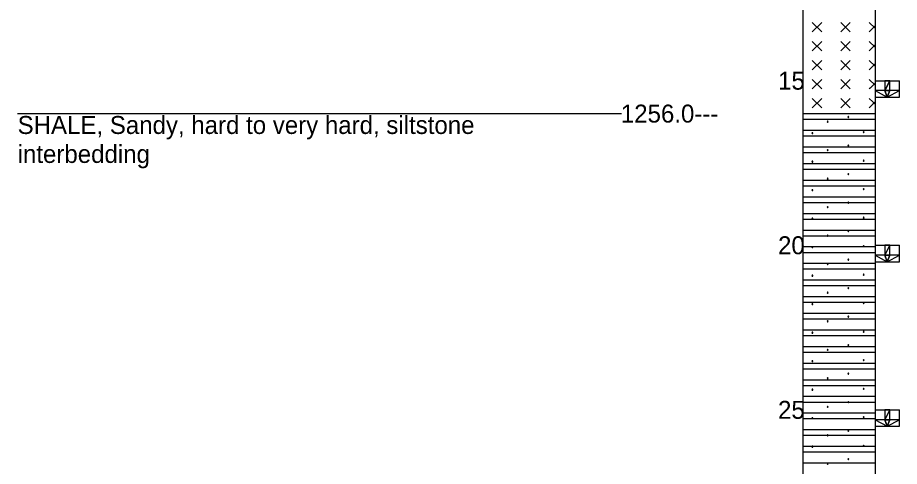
# Model space of a CAD drawing. Extents: x 2150161.5 to 2150203.1, y 143779.5 to 143868.5.
# Drawn here: x 2150186.76 to 2150192.84, y 143849.37 to 143852.47 of the extents above; entities that cross this region are included whole.
import ezdxf

# ---------------------------------------------------------------- set-up
doc = ezdxf.new("R2010")
doc.units = 0
doc.layers.add('Default', color=7, linetype='Continuous')

msp = doc.modelspace()

# ---------------------------------------------------------------- linework, layer by layer
at = {"layer": 'Default'}
for points in [[(2150192.1772, 143855.4435), (2150192.1772, 143843.2844)], [(2150192.6772, 143855.4435), (2150192.6772, 143843.2844)], [(2150192.3084, 143852.4371), (2150192.2428, 143852.3715)], [(2150192.2428, 143852.4371), (2150192.3084, 143852.3715)], [(2150192.5053, 143852.4371), (2150192.4396, 143852.3715)], [(2150192.4396, 143852.4371), (2150192.5053, 143852.3715)], [(2150192.6365, 143852.4371), (2150192.6772, 143852.3964)], [(2150192.6772, 143852.4121), (2150192.6365, 143852.3715)], [(2150192.3084, 143852.3058), (2150192.2428, 143852.2402)], [(2150192.2428, 143852.3058), (2150192.3084, 143852.2402)], [(2150192.5053, 143852.3058), (2150192.4396, 143852.2402)], [(2150192.4396, 143852.3058), (2150192.5053, 143852.2402)], [(2150192.6365, 143852.3058), (2150192.6772, 143852.2652)], [(2150192.6772, 143852.2809), (2150192.6365, 143852.2402)], [(2150192.3084, 143852.1746), (2150192.2428, 143852.109)], [(2150192.2428, 143852.1746), (2150192.3084, 143852.109)], [(2150192.5053, 143852.1746), (2150192.4396, 143852.109)], [(2150192.4396, 143852.1746), (2150192.5053, 143852.109)], [(2150192.6365, 143852.1746), (2150192.6772, 143852.1339)], [(2150192.6772, 143852.1497), (2150192.6365, 143852.109)], [(2150192.3084, 143852.0434), (2150192.2428, 143851.9778)], [(2150192.2428, 143852.0434), (2150192.3084, 143851.9778)], [(2150192.5053, 143852.0434), (2150192.4396, 143851.9778)], [(2150192.4396, 143852.0434), (2150192.5053, 143851.9778)], [(2150192.6365, 143852.0434), (2150192.6772, 143852.0027)], [(2150192.6772, 143852.0184), (2150192.642, 143851.9832), (2150192.6365, 143851.9778)], [(2150192.6772, 143852.0344), (2150192.8438, 143852.0344)], [(2150192.8438, 143851.9208), (2150192.8438, 143852.0344)], [(2150192.3084, 143851.9121), (2150192.2428, 143851.8465)], [(2150192.2428, 143851.9121), (2150192.3084, 143851.8465)], [(2150192.5053, 143851.9121), (2150192.4396, 143851.8465)], [(2150192.4396, 143851.9121), (2150192.5053, 143851.8465)], [(2150192.6365, 143851.9121), (2150192.6611, 143851.8875), (2150192.6772, 143851.8715)], [(2150192.6772, 143851.8872), (2150192.6638, 143851.8739), (2150192.6365, 143851.8465)], [(2150192.6772, 143851.9208), (2150192.8438, 143851.9208)], [(2150186.7605, 143851.8072), (2150190.9272, 143851.8072)], [(2150192.1772, 143851.8072), (2150192.6772, 143851.8072)], [(2150192.1772, 143851.8072), (2150192.6772, 143851.8072)], [(2150192.1772, 143851.7678), (2150192.6772, 143851.7678)], [(2150192.3522, 143851.7513), (2150192.3506, 143851.7542), (2150192.3473, 143851.7542), (2150192.3457, 143851.7514), (2150192.3473, 143851.7485), (2150192.3506, 143851.7485), (2150192.3522, 143851.7513)], [(2150192.4948, 143851.7832), (2150192.4932, 143851.786), (2150192.4899, 143851.786), (2150192.4883, 143851.7832), (2150192.4899, 143851.7804), (2150192.4932, 143851.7804), (2150192.4948, 143851.7832)], [(2150192.1772, 143851.6923), (2150192.6772, 143851.6923)], [(2150192.1772, 143851.653), (2150192.6772, 143851.653)], [(2150192.2476, 143851.6724), (2150192.2459, 143851.6752), (2150192.2427, 143851.6752), (2150192.241, 143851.6724), (2150192.2427, 143851.6695), (2150192.2459, 143851.6695), (2150192.2476, 143851.6724)], [(2150192.6003, 143851.6789), (2150192.5987, 143851.6818), (2150192.5954, 143851.6818), (2150192.5938, 143851.6789), (2150192.5954, 143851.6761), (2150192.5987, 143851.6761), (2150192.6003, 143851.6789)], [(2150192.1772, 143851.5775), (2150192.6772, 143851.5775)], [(2150192.4948, 143851.5864), (2150192.4932, 143851.5892), (2150192.4899, 143851.5892), (2150192.4883, 143851.5864), (2150192.4899, 143851.5835), (2150192.4932, 143851.5835), (2150192.4948, 143851.5864)], [(2150192.1772, 143851.5381), (2150192.6772, 143851.5381)], [(2150192.3522, 143851.5545), (2150192.3506, 143851.5574), (2150192.3473, 143851.5574), (2150192.3457, 143851.5545), (2150192.3473, 143851.5516), (2150192.3506, 143851.5516), (2150192.3522, 143851.5545)], [(2150192.1772, 143851.4627), (2150192.6772, 143851.4627)], [(2150192.2476, 143851.4755), (2150192.2459, 143851.4783), (2150192.2427, 143851.4783), (2150192.241, 143851.4755), (2150192.2427, 143851.4726), (2150192.2459, 143851.4726), (2150192.2476, 143851.4755)], [(2150192.6003, 143851.482), (2150192.5987, 143851.4849), (2150192.5954, 143851.4849), (2150192.5938, 143851.482), (2150192.5954, 143851.4792), (2150192.5987, 143851.4792), (2150192.6003, 143851.482)], [(2150192.1772, 143851.4233), (2150192.6772, 143851.4233)], [(2150192.4948, 143851.3895), (2150192.4932, 143851.3923), (2150192.4899, 143851.3923), (2150192.4883, 143851.3895), (2150192.4899, 143851.3867), (2150192.4932, 143851.3867), (2150192.4948, 143851.3895)], [(2150192.1772, 143851.3478), (2150192.6772, 143851.3478)], [(2150192.3522, 143851.3576), (2150192.3506, 143851.3605), (2150192.3473, 143851.3605), (2150192.3457, 143851.3577), (2150192.3473, 143851.3548), (2150192.3506, 143851.3548), (2150192.3522, 143851.3576)], [(2150192.1772, 143851.3085), (2150192.6772, 143851.3085)], [(2150192.2476, 143851.2787), (2150192.2459, 143851.2815), (2150192.2427, 143851.2815), (2150192.241, 143851.2787), (2150192.2427, 143851.2758), (2150192.2459, 143851.2758), (2150192.2476, 143851.2787)], [(2150192.6003, 143851.2852), (2150192.5987, 143851.2881), (2150192.5954, 143851.2881), (2150192.5938, 143851.2852), (2150192.5954, 143851.2824), (2150192.5987, 143851.2824), (2150192.6003, 143851.2852)], [(2150192.1772, 143851.233), (2150192.6772, 143851.233)], [(2150192.1772, 143851.1936), (2150192.6772, 143851.1936)], [(2150192.3522, 143851.1608), (2150192.3506, 143851.1637), (2150192.3473, 143851.1637), (2150192.3457, 143851.1608), (2150192.3473, 143851.1579), (2150192.3506, 143851.1579), (2150192.3522, 143851.1608)], [(2150192.4948, 143851.1927), (2150192.4932, 143851.1955), (2150192.4899, 143851.1955), (2150192.4883, 143851.1927), (2150192.4899, 143851.1898), (2150192.4932, 143851.1898), (2150192.4948, 143851.1927)], [(2150192.1772, 143851.1182), (2150192.6772, 143851.1182)], [(2150192.2476, 143851.0818), (2150192.2459, 143851.0846), (2150192.2427, 143851.0846), (2150192.241, 143851.0818), (2150192.2427, 143851.0789), (2150192.2459, 143851.0789), (2150192.2476, 143851.0818)], [(2150192.6003, 143851.0883), (2150192.5987, 143851.0912), (2150192.5954, 143851.0912), (2150192.5938, 143851.0883), (2150192.5954, 143851.0855), (2150192.5987, 143851.0855), (2150192.6003, 143851.0883)], [(2150192.1772, 143851.0788), (2150192.6772, 143851.0788)], [(2150192.1772, 143851.0033), (2150192.6772, 143851.0033)], [(2150192.1772, 143850.964), (2150192.6772, 143850.964)], [(2150192.3522, 143850.9639), (2150192.3506, 143850.9668), (2150192.3473, 143850.9668), (2150192.3457, 143850.964), (2150192.3473, 143850.9611), (2150192.3506, 143850.9611), (2150192.3522, 143850.9639)], [(2150192.4948, 143850.9958), (2150192.4932, 143850.9986), (2150192.4899, 143850.9986), (2150192.4883, 143850.9958), (2150192.4899, 143850.993), (2150192.4932, 143850.993), (2150192.4948, 143850.9958)], [(2150192.6772, 143850.8981), (2150192.8438, 143850.8981)], [(2150192.8438, 143850.7844), (2150192.8438, 143850.8981)], [(2150192.1772, 143850.8885), (2150192.6772, 143850.8885)], [(2150192.1772, 143850.8492), (2150192.6772, 143850.8492)], [(2150192.2476, 143850.885), (2150192.2459, 143850.8878), (2150192.2427, 143850.8878), (2150192.241, 143850.885), (2150192.2427, 143850.8821), (2150192.2459, 143850.8821), (2150192.2476, 143850.885)], [(2150192.6003, 143850.8915), (2150192.5987, 143850.8944), (2150192.5954, 143850.8944), (2150192.5938, 143850.8915), (2150192.5954, 143850.8887), (2150192.5987, 143850.8887), (2150192.6003, 143850.8915)], [(2150192.4948, 143850.799), (2150192.4932, 143850.8018), (2150192.4899, 143850.8018), (2150192.4883, 143850.799), (2150192.4899, 143850.7961), (2150192.4932, 143850.7961), (2150192.4948, 143850.799)], [(2150192.6772, 143850.7844), (2150192.8438, 143850.7844)], [(2150192.1772, 143850.7737), (2150192.6772, 143850.7737)], [(2150192.1772, 143850.7343), (2150192.6772, 143850.7343)], [(2150192.3522, 143850.7671), (2150192.3506, 143850.77), (2150192.3473, 143850.77), (2150192.3457, 143850.7671), (2150192.3473, 143850.7642), (2150192.3506, 143850.7642), (2150192.3522, 143850.7671)], [(2150192.1772, 143850.6589), (2150192.6772, 143850.6589)], [(2150192.2476, 143850.6881), (2150192.2459, 143850.6909), (2150192.2427, 143850.6909), (2150192.241, 143850.6881), (2150192.2427, 143850.6852), (2150192.2459, 143850.6852), (2150192.2476, 143850.6881)], [(2150192.6003, 143850.6946), (2150192.5987, 143850.6975), (2150192.5954, 143850.6975), (2150192.5938, 143850.6946), (2150192.5954, 143850.6918), (2150192.5987, 143850.6918), (2150192.6003, 143850.6946)], [(2150192.1772, 143850.6195), (2150192.6772, 143850.6195)], [(2150192.4948, 143850.6021), (2150192.4932, 143850.6049), (2150192.4899, 143850.6049), (2150192.4883, 143850.6021), (2150192.4899, 143850.5993), (2150192.4932, 143850.5993), (2150192.4948, 143850.6021)], [(2150192.1772, 143850.544), (2150192.6772, 143850.544)], [(2150192.3522, 143850.5702), (2150192.3506, 143850.5731), (2150192.3473, 143850.5731), (2150192.3457, 143850.5703), (2150192.3473, 143850.5674), (2150192.3506, 143850.5674), (2150192.3522, 143850.5702)], [(2150192.1772, 143850.5047), (2150192.6772, 143850.5047)], [(2150192.2476, 143850.4913), (2150192.2459, 143850.4941), (2150192.2427, 143850.4941), (2150192.241, 143850.4913), (2150192.2427, 143850.4884), (2150192.2459, 143850.4884), (2150192.2476, 143850.4913)], [(2150192.6003, 143850.4978), (2150192.5987, 143850.5007), (2150192.5954, 143850.5007), (2150192.5938, 143850.4978), (2150192.5954, 143850.495), (2150192.5987, 143850.495), (2150192.6003, 143850.4978)], [(2150192.1772, 143850.4292), (2150192.6772, 143850.4292)], [(2150192.1772, 143850.3898), (2150192.6772, 143850.3898)], [(2150192.3522, 143850.3734), (2150192.3506, 143850.3763), (2150192.3473, 143850.3763), (2150192.3457, 143850.3734), (2150192.3473, 143850.3705), (2150192.3506, 143850.3705), (2150192.3522, 143850.3734)], [(2150192.4948, 143850.4053), (2150192.4932, 143850.4081), (2150192.4899, 143850.4081), (2150192.4883, 143850.4053), (2150192.4899, 143850.4024), (2150192.4932, 143850.4024), (2150192.4948, 143850.4053)], [(2150192.1772, 143850.3144), (2150192.6772, 143850.3144)], [(2150192.2476, 143850.2944), (2150192.2459, 143850.2972), (2150192.2427, 143850.2972), (2150192.241, 143850.2944), (2150192.2427, 143850.2915), (2150192.2459, 143850.2915), (2150192.2476, 143850.2944)], [(2150192.6003, 143850.3009), (2150192.5987, 143850.3038), (2150192.5954, 143850.3038), (2150192.5938, 143850.3009), (2150192.5954, 143850.2981), (2150192.5987, 143850.2981), (2150192.6003, 143850.3009)], [(2150192.1772, 143850.275), (2150192.6772, 143850.275)], [(2150192.1772, 143850.1995), (2150192.6772, 143850.1995)], [(2150192.3522, 143850.1765), (2150192.3506, 143850.1794), (2150192.3473, 143850.1794), (2150192.3457, 143850.1766), (2150192.3473, 143850.1737), (2150192.3506, 143850.1737), (2150192.3522, 143850.1765)], [(2150192.4948, 143850.2084), (2150192.4932, 143850.2112), (2150192.4899, 143850.2112), (2150192.4883, 143850.2084), (2150192.4899, 143850.2056), (2150192.4932, 143850.2056), (2150192.4948, 143850.2084)], [(2150192.1772, 143850.1602), (2150192.6772, 143850.1602)], [(2150192.6003, 143850.1041), (2150192.5987, 143850.107), (2150192.5954, 143850.107), (2150192.5938, 143850.1041), (2150192.5954, 143850.1013), (2150192.5987, 143850.1013), (2150192.6003, 143850.1041)], [(2150192.1772, 143850.0847), (2150192.6772, 143850.0847)], [(2150192.1772, 143850.0453), (2150192.6772, 143850.0453)], [(2150192.2476, 143850.0976), (2150192.2459, 143850.1004), (2150192.2427, 143850.1004), (2150192.241, 143850.0976), (2150192.2427, 143850.0947), (2150192.2459, 143850.0947), (2150192.2476, 143850.0976)], [(2150192.4948, 143850.0116), (2150192.4932, 143850.0144), (2150192.4899, 143850.0144), (2150192.4883, 143850.0116), (2150192.4899, 143850.0087), (2150192.4932, 143850.0087), (2150192.4948, 143850.0116)], [(2150192.1772, 143849.9699), (2150192.6772, 143849.9699)], [(2150192.1772, 143849.9305), (2150192.6772, 143849.9305)], [(2150192.3522, 143849.9797), (2150192.3506, 143849.9826), (2150192.3473, 143849.9826), (2150192.3457, 143849.9797), (2150192.3473, 143849.9768), (2150192.3506, 143849.9768), (2150192.3522, 143849.9797)], [(2150192.2476, 143849.9007), (2150192.2459, 143849.9035), (2150192.2427, 143849.9035), (2150192.241, 143849.9007), (2150192.2427, 143849.8978), (2150192.2459, 143849.8978), (2150192.2476, 143849.9007)], [(2150192.6003, 143849.9072), (2150192.5987, 143849.9101), (2150192.5954, 143849.9101), (2150192.5938, 143849.9072), (2150192.5954, 143849.9044), (2150192.5987, 143849.9044), (2150192.6003, 143849.9072)], [(2150192.1772, 143849.8551), (2150192.6772, 143849.8551)], [(2150192.1772, 143849.8157), (2150192.6772, 143849.8157)], [(2150192.4948, 143849.8147), (2150192.4932, 143849.8175), (2150192.4899, 143849.8175), (2150192.4883, 143849.8147), (2150192.4899, 143849.8119), (2150192.4932, 143849.8119), (2150192.4948, 143849.8147)], [(2150192.3522, 143849.7828), (2150192.3506, 143849.7857), (2150192.3473, 143849.7857), (2150192.3457, 143849.7829), (2150192.3473, 143849.78), (2150192.3506, 143849.78), (2150192.3522, 143849.7828)], [(2150192.6772, 143849.7617), (2150192.8438, 143849.7617)], [(2150192.8438, 143849.6481), (2150192.8438, 143849.7617)], [(2150192.1772, 143849.7402), (2150192.6772, 143849.7402)], [(2150192.1772, 143849.7009), (2150192.6772, 143849.7009)], [(2150192.2476, 143849.7039), (2150192.2459, 143849.7067), (2150192.2427, 143849.7067), (2150192.241, 143849.7039), (2150192.2427, 143849.701), (2150192.2459, 143849.701), (2150192.2476, 143849.7039)], [(2150192.6003, 143849.7104), (2150192.5987, 143849.7133), (2150192.5954, 143849.7133), (2150192.5938, 143849.7104), (2150192.5954, 143849.7076), (2150192.5987, 143849.7076), (2150192.6003, 143849.7104)], [(2150192.1772, 143849.6254), (2150192.6772, 143849.6254)], [(2150192.4948, 143849.6179), (2150192.4932, 143849.6207), (2150192.4899, 143849.6207), (2150192.4883, 143849.6179), (2150192.4899, 143849.615), (2150192.4932, 143849.615), (2150192.4948, 143849.6179)], [(2150192.6772, 143849.6481), (2150192.8438, 143849.6481)], [(2150192.1772, 143849.586), (2150192.6772, 143849.586)], [(2150192.3522, 143849.586), (2150192.3506, 143849.5889), (2150192.3473, 143849.5889), (2150192.3457, 143849.586), (2150192.3473, 143849.5831), (2150192.3506, 143849.5831), (2150192.3522, 143849.586)], [(2150192.1772, 143849.5106), (2150192.6772, 143849.5106)], [(2150192.2476, 143849.507), (2150192.2459, 143849.5098), (2150192.2427, 143849.5098), (2150192.241, 143849.507), (2150192.2427, 143849.5041), (2150192.2459, 143849.5041), (2150192.2476, 143849.507)], [(2150192.6003, 143849.5135), (2150192.5987, 143849.5164), (2150192.5954, 143849.5164), (2150192.5938, 143849.5135), (2150192.5954, 143849.5107), (2150192.5987, 143849.5107), (2150192.6003, 143849.5135)], [(2150192.1772, 143849.4712), (2150192.6772, 143849.4712)], [(2150192.1772, 143849.3957), (2150192.6772, 143849.3957)], [(2150192.3522, 143849.3891), (2150192.3506, 143849.392), (2150192.3473, 143849.392), (2150192.3457, 143849.3892), (2150192.3473, 143849.3863), (2150192.3506, 143849.3863), (2150192.3522, 143849.3891)], [(2150192.4948, 143849.421), (2150192.4932, 143849.4238), (2150192.4899, 143849.4238), (2150192.4883, 143849.421), (2150192.4899, 143849.4182), (2150192.4932, 143849.4182), (2150192.4948, 143849.421)]]:
    msp.add_lwpolyline(points, dxfattribs=at)
for points in [[(2150192.7438, 143851.9662), (2150192.7772, 143851.9662), (2150192.7772, 143852.0344), (2150192.7438, 143851.9662)], [(2150192.7438, 143851.9662), (2150192.7772, 143852.0344), (2150192.7438, 143852.0344), (2150192.7438, 143851.9662)], [(2150192.7438, 143851.9662), (2150192.6772, 143851.9662), (2150192.7605, 143851.9208), (2150192.7438, 143851.9662)], [(2150192.7438, 143851.9662), (2150192.7605, 143851.9208), (2150192.7772, 143851.9662), (2150192.7438, 143851.9662)], [(2150192.7605, 143851.9208), (2150192.8438, 143851.9662), (2150192.7772, 143851.9662), (2150192.7605, 143851.9208)], [(2150192.7438, 143850.8299), (2150192.7772, 143850.8299), (2150192.7772, 143850.8981), (2150192.7438, 143850.8299)], [(2150192.7438, 143850.8299), (2150192.7772, 143850.8981), (2150192.7438, 143850.8981), (2150192.7438, 143850.8299)], [(2150192.7438, 143850.8299), (2150192.6772, 143850.8299), (2150192.7605, 143850.7844), (2150192.7438, 143850.8299)], [(2150192.7438, 143850.8299), (2150192.7605, 143850.7844), (2150192.7772, 143850.8299), (2150192.7438, 143850.8299)], [(2150192.7605, 143850.7844), (2150192.8438, 143850.8299), (2150192.7772, 143850.8299), (2150192.7605, 143850.7844)], [(2150192.7438, 143849.6935), (2150192.7772, 143849.6935), (2150192.7772, 143849.7617), (2150192.7438, 143849.6935)], [(2150192.7438, 143849.6935), (2150192.7772, 143849.7617), (2150192.7438, 143849.7617), (2150192.7438, 143849.6935)], [(2150192.7438, 143849.6935), (2150192.6772, 143849.6935), (2150192.7605, 143849.6481), (2150192.7438, 143849.6935)], [(2150192.7438, 143849.6935), (2150192.7605, 143849.6481), (2150192.7772, 143849.6935), (2150192.7438, 143849.6935)], [(2150192.7605, 143849.6481), (2150192.8438, 143849.6935), (2150192.7772, 143849.6935), (2150192.7605, 143849.6481)]]:
    msp.add_lwpolyline(points, close=True, dxfattribs=at)

# ---------------------------------------------------------------- texts
for s, p in [('15', (2150192.0068, 143851.9724)), ('1256.0---', (2150190.9223, 143851.7452)), ('SHALE, Sandy, hard to very hard, siltstone', (2150186.7605, 143851.6665)), ('interbedding', (2150186.7605, 143851.4665)), ('20', (2150192.0068, 143850.8361)), ('25', (2150192.0068, 143849.6997))]:
    msp.add_text(s, height=0.124, dxfattribs=at).set_placement(p)

doc.saveas('drawing.dxf')
